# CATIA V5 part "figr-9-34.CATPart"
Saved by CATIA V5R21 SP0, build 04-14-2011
Part number: Part1
Bounding box of the stored display mesh (mm): x -250 to 0, y -60 to 60, z 0 to 100
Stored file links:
  D:\CATIA V5R21 E-RESOURCES\CATIA-V5R21\catia-v5r21-prt\c09-catia-v5r20-prt\c09-catia-v5r21-figr-9-34.CATPart
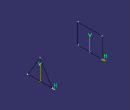
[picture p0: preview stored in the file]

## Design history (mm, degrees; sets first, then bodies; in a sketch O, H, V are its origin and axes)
Body1 (main body)
  Sketch1 on yz-plane, origin (0, 0, 0), H (0, 1, 0), V (0, 0, 1)
    point P1 (-60, 0)
    line L1 (-60, 0) -> (0, 100)
    point P2 (0, 100)
    line L2 (0, 100) -> (60, 0)
    point P3 (60, 0)
    line L3 (60, 0) -> (-60, 0)
    coincidence: P1 H, P2 V, P3 H
    horizontal: L3 H
    midpoint: O L3
  Sketch2, origin (-250, 0, 0), H (0, 1, 0), V (0, 0, 1)
    point P1 (-60, 0)
    line L1 (-60, 0) -> (60, 0)
    line L2 (60, 0) -> (60, 100)
    line L3 (60, 100) -> (-60, 100)
    line L4 (-60, 100) -> (-60, 0)
    coincidence: P1 H
    horizontal: L1 H, L3 H
    vertical: L2 V, L4 V
  Loft1: Sections (Sketch1; Sketch2), SectionCouplingPoints ({coupling CouplingPoints (vertex [element of Sketch1 | element of Sketch1]; vertex [element of Sketch2 | element of Sketch2])}; {coupling CouplingPoints (vertex [element of Sketch1 | element of Sketch1]; vertex [element of Sketch2 | element of Sketch2])}; {coupling CouplingPoints (vertex [element of Sketch1 | element of Sketch1]; vertex [element of Sketch2 | element of Sketch2])})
